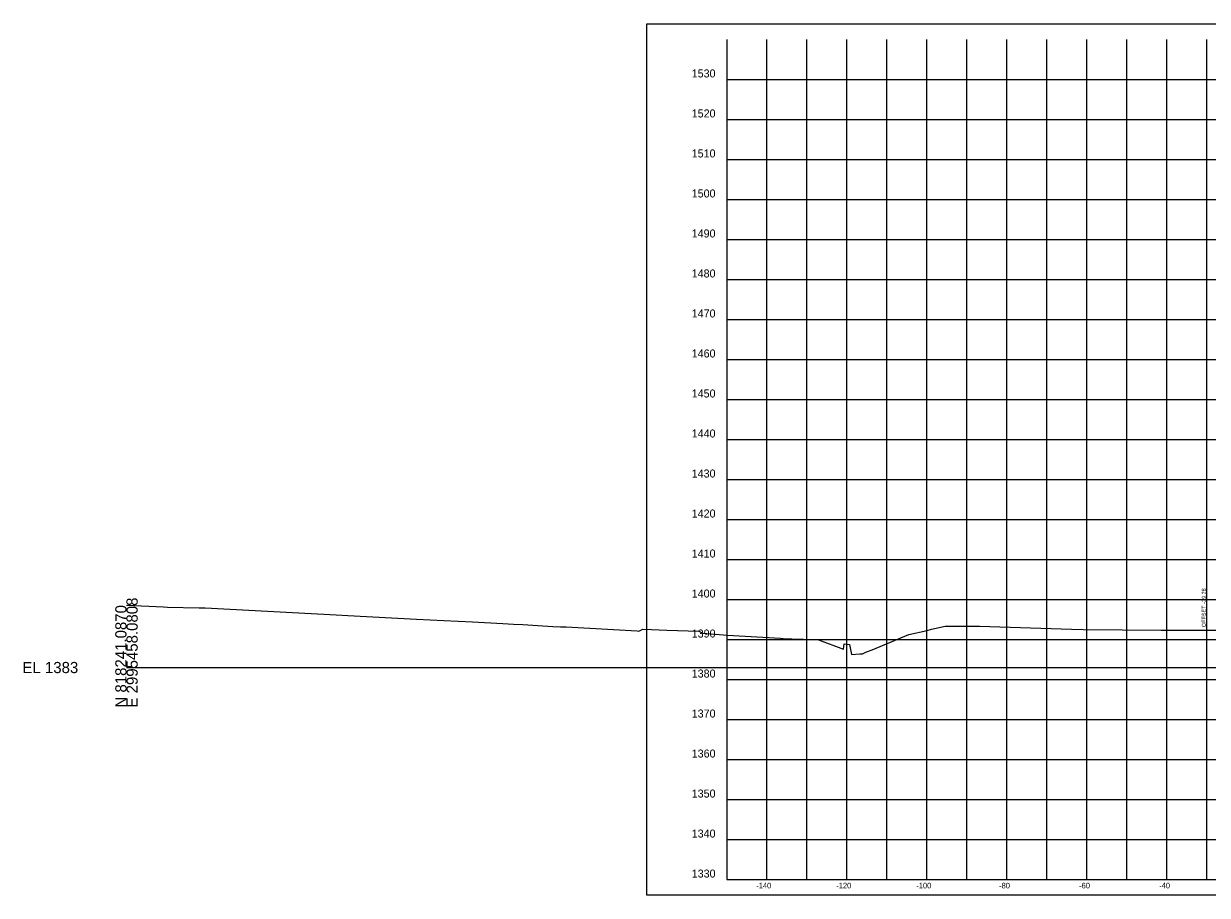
# Model space of a CAD drawing. Extents: x -26 to 603, y -10 to 2564.
# Drawn here: x -25.7 to 270.1, y 943.1 to 1160.9 of the extents above; entities that cross this region are included whole.
import ezdxf

# ---------------------------------------------------------------- set-up
doc = ezdxf.new("R2010")
doc.units = 0
for name, color, linetype in [('DESIGN - SHEET - Corner Text', 7, 'Continuous'), ('DESIGN - SHEET - Light Grid', 7, 'Continuous'), ('DESIGN - SHEET - Linework', 7, 'Continuous'), ('DESIGN - SHEET - Plot Shape', 7, 'Continuous'), ('DESIGN - TYPICAL - Slope Tie Text', 7, 'Continuous'), ('SURVEY - GROUND - Top of Ground', 7, 'Continuous')]:
    doc.layers.add(name, color=color, linetype=linetype)

msp = doc.modelspace()

# ---------------------------------------------------------------- linework, layer by layer
at = {"layer": 'DESIGN - SHEET - Light Grid'}
msp.add_line((0, 1000), (300, 1000), dxfattribs=at)
at = {"layer": 'DESIGN - SHEET - Linework'}
for p, q in [((160, 947), (160, 1157)), ((170, 947), (170, 1157)), ((180, 947), (180, 1157)), ((190, 947), (190, 1157)), ((200, 947), (200, 1157)), ((210, 947), (210, 1157)), ((220, 947), (220, 1157)), ((230, 947), (230, 1157)), ((240, 947), (240, 1157)), ((250, 947), (250, 1157)), ((260, 947), (260, 1157)), ((270, 947), (270, 1157)), ((150, 1147), (450, 1147)), ((150, 1137), (450, 1137)), ((150, 1127), (450, 1127)), ((150, 1117), (450, 1117)), ((150, 1107), (450, 1107)), ((150, 1097), (450, 1097)), ((150, 1087), (450, 1087)), ((150, 1077), (450, 1077)), ((150, 1067), (450, 1067)), ((150, 1057), (450, 1057)), ((150, 1047), (450, 1047)), ((150, 1037), (450, 1037)), ((150, 1027), (450, 1027)), ((150, 1017), (450, 1017)), ((150, 1007), (450, 1007)), ((150, 997), (450, 997)), ((150, 987), (450, 987)), ((150, 977), (450, 977)), ((150, 967), (450, 967)), ((150, 957), (450, 957))]:
    msp.add_line(p, q, dxfattribs=at)
msp.add_lwpolyline([(150, 1157), (150, 947), (450, 947), (450, 1157)], dxfattribs=at)
at = {"layer": 'DESIGN - SHEET - Plot Shape'}
msp.add_lwpolyline([(130, 1160.94), (470, 1160.94), (470, 943.06), (130, 943.06)], close=True, dxfattribs=at)
at = {"layer": 'SURVEY - GROUND - Top of Ground'}
msp.add_lwpolyline([(0, 1015.55), (9.23, 1015.14), (10.29, 1015.09), (18.13, 1014.95), (19.7, 1014.92), (52.38, 1013.15), (55.34, 1012.99), (72.46, 1012.12), (79.28, 1011.74), (86.5, 1011.46), (94.08, 1011.01), (96.7, 1010.83), (99.01, 1010.74), (106.54, 1010.23), (108.46, 1010.19), (109.86, 1010.14), (127.62, 1009.16), (128.05, 1009.13), (128.56, 1009.38), (129.06, 1009.58), (131.19, 1009.52), (135.06, 1009.37), (143.06, 1009.06), (144, 1008.56), (147.14, 1008.34), (150.17, 1008.13), (163.4, 1007.32), (164.09, 1007.28), (166.28, 1007.21), (169.17, 1007.07), (172.96, 1006.89), (179.16, 1004.61), (179.34, 1005.95), (180.69, 1005.76), (181.15, 1003.24), (183.29, 1003.41), (183.89, 1003.4), (184.93, 1003.9), (186.32, 1004.42), (195.49, 1008.25), (200.06, 1009.29), (201.19, 1009.61), (204.57, 1010.32), (212.51, 1010.37), (213.14, 1010.36), (236.19, 1009.6), (239.06, 1009.52), (258.6, 1009.36), (272.55, 1009.32)], dxfattribs=at)

# ---------------------------------------------------------------- texts
at = {"layer": 'DESIGN - SHEET - Corner Text'}
for s, height, p in [('1530', 2, (141.25, 1147.5)), ('1520', 2, (141.25, 1137.5)), ('1510', 2, (141.25, 1127.5)), ('1500', 2, (141.25, 1117.5)), ('1490', 2, (141.25, 1107.5)), ('1480', 2, (141.25, 1097.5)), ('1470', 2, (141.25, 1087.5)), ('1460', 2, (141.25, 1077.5)), ('1450', 2, (141.25, 1067.5)), ('1440', 2, (141.25, 1057.5)), ('1430', 2, (141.25, 1047.5)), ('1420', 2, (141.25, 1037.5)), ('1410', 2, (141.25, 1027.5)), ('1400', 2, (141.25, 1017.5)), ('1390', 2, (141.25, 1007.5)), ('1380', 2, (141.25, 997.5)), ('1370', 2, (141.25, 987.5)), ('1360', 2, (141.25, 977.5)), ('1350', 2, (141.25, 967.5)), ('1340', 2, (141.25, 957.5)), ('1330', 2, (141.25, 947.5)), ('-140', 1.4, (157.37, 944.8)), ('-120', 1.4, (177.37, 944.8)), ('-100', 1.4, (197.37, 944.8)), ('-80', 1.4, (218.06, 944.8)), ('-60', 1.4, (238.06, 944.8)), ('-40', 1.4, (258.06, 944.8))]:
    msp.add_text(s, height=height, dxfattribs=at).set_placement(p)
at = {"layer": 'DESIGN - SHEET - Light Grid'}
for s, p in [('N 818241.0870', (0, 990)), ('E 2995458.0808', (2.8, 990))]:
    msp.add_text(s, height=2.8, rotation=90, dxfattribs=at).set_placement(p)
msp.add_text('EL 1383', height=2.8, dxfattribs=at).set_placement((-26, 998.6))
at = {"layer": 'DESIGN - TYPICAL - Slope Tie Text'}
msp.add_text('OFFSET -29.28', height=1, rotation=90, dxfattribs=at).set_placement((269.72, 1010.07))

doc.saveas('drawing.dxf')
